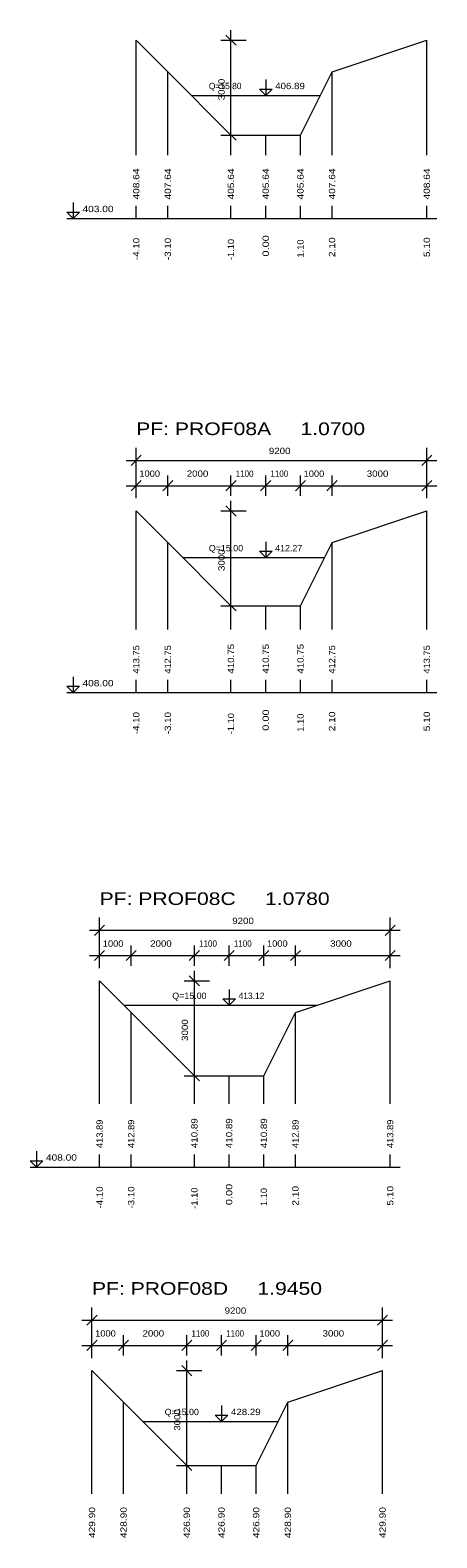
# Model space of a CAD drawing. Extents: x 7 to 442, y -393 to 441.
# Drawn here: x 175.74 to 188.62, y 95.9 to 143.59 of the extents above; entities that cross this region are included whole.
import ezdxf

# ---------------------------------------------------------------- set-up
doc = ezdxf.new("R2010")
doc.units = 0
doc.header["$LTSCALE"] = 0.08
doc.layers.add('7', color=7, linetype='Continuous', lineweight=13)

msp = doc.modelspace()

# ---------------------------------------------------------------- linework, layer by layer
at = {"layer": '7'}
for p, q in [((182.101, 140.111), (182.101, 143.591)), ((179.101, 139.634), (179.101, 143.271)), ((181.781, 143.271), (182.581, 143.271)), ((182.261, 143.111), (181.941, 143.431)), ((188.301, 139.634), (188.301, 143.271)), ((180.101, 139.634), (180.101, 142.271)), ((185.301, 139.634), (185.301, 142.271)), ((180.847, 141.525), (184.928, 141.525)), ((181.781, 140.271), (182.581, 140.271)), ((182.261, 140.111), (181.941, 140.431)), ((182.101, 139.634), (182.101, 140.271)), ((183.201, 139.634), (183.201, 140.271)), ((184.301, 139.634), (184.301, 140.271)), ((179.101, 137.634), (179.101, 138.034)), ((180.101, 137.634), (180.101, 138.034)), ((182.101, 137.634), (182.101, 138.034)), ((183.201, 137.634), (183.201, 138.034)), ((184.301, 137.634), (184.301, 138.034)), ((185.301, 137.634), (185.301, 138.034)), ((188.301, 137.634), (188.301, 138.034)), ((176.901, 137.634), (188.621, 137.634)), ((179.101, 128.781), (179.101, 130.381)), ((188.301, 128.781), (188.301, 130.381)), ((178.781, 129.981), (188.621, 129.981)), ((178.941, 129.821), (179.261, 130.141)), ((188.141, 129.821), (188.461, 130.141)), ((178.941, 129.021), (179.261, 129.341)), ((179.101, 128.861), (179.101, 129.501)), ((179.941, 129.021), (180.261, 129.341)), ((180.101, 128.861), (180.101, 129.501)), ((181.941, 129.021), (182.261, 129.341)), ((182.101, 128.861), (182.101, 129.501)), ((183.041, 129.021), (183.361, 129.341)), ((183.201, 128.861), (183.201, 129.501)), ((184.141, 129.021), (184.461, 129.341)), ((184.301, 128.861), (184.301, 129.501)), ((185.141, 129.021), (185.461, 129.341)), ((185.301, 128.861), (185.301, 129.501)), ((188.141, 129.021), (188.461, 129.341)), ((188.301, 128.861), (188.301, 129.501)), ((178.781, 129.181), (188.621, 129.181)), ((179.101, 124.634), (179.101, 128.381)), ((181.781, 128.381), (182.581, 128.381)), ((182.261, 128.221), (181.941, 128.541)), ((182.101, 125.221), (182.101, 128.701)), ((188.301, 124.634), (188.301, 128.381)), ((180.101, 124.634), (180.101, 127.381)), ((185.301, 124.634), (185.301, 127.381)), ((180.577, 126.904), (185.063, 126.904)), ((182.261, 125.221), (181.941, 125.541)), ((181.781, 125.381), (182.581, 125.381)), ((182.101, 124.634), (182.101, 125.381)), ((183.201, 124.634), (183.201, 125.381)), ((184.301, 124.634), (184.301, 125.381)), ((176.901, 122.634), (188.621, 122.634)), ((179.101, 122.634), (179.101, 123.034)), ((180.101, 122.634), (180.101, 123.034)), ((182.101, 122.634), (182.101, 123.034)), ((183.201, 122.634), (183.201, 123.034)), ((184.301, 122.634), (184.301, 123.034)), ((185.301, 122.634), (185.301, 123.034)), ((188.301, 122.634), (188.301, 123.034)), ((177.942, 113.916), (177.942, 115.516)), ((187.142, 113.916), (187.142, 115.516)), ((177.622, 115.116), (187.462, 115.116)), ((177.782, 114.956), (178.102, 115.276)), ((186.982, 114.956), (187.302, 115.276)), ((177.782, 114.156), (178.102, 114.476)), ((177.942, 113.996), (177.942, 114.636)), ((178.782, 114.156), (179.102, 114.476)), ((178.942, 113.996), (178.942, 114.636)), ((180.782, 114.156), (181.102, 114.476)), ((180.942, 113.996), (180.942, 114.636)), ((181.882, 114.156), (182.202, 114.476)), ((182.042, 113.996), (182.042, 114.636)), ((182.982, 114.156), (183.302, 114.476)), ((183.142, 113.996), (183.142, 114.636)), ((183.982, 114.156), (184.302, 114.476)), ((184.142, 113.996), (184.142, 114.636)), ((186.982, 114.156), (187.302, 114.476)), ((187.142, 113.996), (187.142, 114.636)), ((177.622, 114.316), (187.462, 114.316)), ((177.942, 109.627), (177.942, 113.516)), ((180.622, 113.516), (181.422, 113.516)), ((181.102, 113.356), (180.782, 113.676)), ((180.942, 110.356), (180.942, 113.836)), ((187.142, 109.627), (187.142, 113.516)), ((178.713, 112.745), (184.829, 112.745)), ((178.942, 109.627), (178.942, 112.516)), ((184.142, 109.627), (184.142, 112.516)), ((181.102, 110.356), (180.782, 110.676)), ((180.622, 110.516), (181.422, 110.516)), ((180.942, 109.627), (180.942, 110.516)), ((182.042, 109.627), (182.042, 110.516)), ((183.142, 109.627), (183.142, 110.516)), ((177.942, 107.627), (177.942, 108.027)), ((178.942, 107.627), (178.942, 108.027)), ((180.942, 107.627), (180.942, 108.027)), ((182.042, 107.627), (182.042, 108.027)), ((183.142, 107.627), (183.142, 108.027)), ((184.142, 107.627), (184.142, 108.027)), ((187.142, 107.627), (187.142, 108.027)), ((175.742, 107.627), (187.462, 107.627)), ((177.701, 101.585), (177.701, 103.185)), ((186.901, 101.585), (186.901, 103.185)), ((177.381, 102.785), (187.221, 102.785)), ((177.541, 102.625), (177.861, 102.945)), ((186.741, 102.625), (187.061, 102.945)), ((177.541, 101.825), (177.861, 102.145)), ((177.701, 101.665), (177.701, 102.305)), ((178.541, 101.825), (178.861, 102.145)), ((178.701, 101.665), (178.701, 102.305)), ((180.541, 101.825), (180.861, 102.145)), ((180.701, 101.665), (180.701, 102.305)), ((181.641, 101.825), (181.961, 102.145)), ((181.801, 101.665), (181.801, 102.305)), ((182.741, 101.825), (183.061, 102.145)), ((182.901, 101.665), (182.901, 102.305)), ((183.741, 101.825), (184.061, 102.145)), ((183.901, 101.665), (183.901, 102.305)), ((186.741, 101.825), (187.061, 102.145)), ((186.901, 101.665), (186.901, 102.305)), ((177.381, 101.985), (187.221, 101.985)), ((177.701, 97.289), (177.701, 101.185)), ((180.381, 101.185), (181.181, 101.185)), ((180.861, 101.025), (180.541, 101.345)), ((180.701, 98.025), (180.701, 101.505)), ((186.901, 97.289), (186.901, 101.185)), ((178.701, 97.289), (178.701, 100.185)), ((183.901, 97.289), (183.901, 100.185)), ((179.307, 99.579), (183.598, 99.579)), ((180.861, 98.025), (180.541, 98.345)), ((180.381, 98.185), (181.181, 98.185)), ((180.701, 97.289), (180.701, 98.185)), ((181.801, 97.289), (181.801, 98.185)), ((182.901, 97.289), (182.901, 98.185))]:
    msp.add_line(p, q, dxfattribs=at)
for points in [[(179.101, 143.271), (180.101, 142.271), (182.101, 140.271), (183.201, 140.271), (184.301, 140.271), (185.301, 142.271), (188.301, 143.271)], [(183.201, 142.025), (183.201, 141.525), (183.001, 141.725), (183.401, 141.725), (183.201, 141.525)], [(177.101, 138.134), (177.101, 137.634), (176.901, 137.834), (177.301, 137.834), (177.101, 137.634)], [(179.101, 128.381), (180.101, 127.381), (182.101, 125.381), (183.201, 125.381), (184.301, 125.381), (185.301, 127.381), (188.301, 128.381)], [(183.201, 127.404), (183.201, 126.904), (183.001, 127.104), (183.401, 127.104), (183.201, 126.904)], [(177.101, 123.134), (177.101, 122.634), (176.901, 122.834), (177.301, 122.834), (177.101, 122.634)], [(177.942, 113.516), (178.942, 112.516), (180.942, 110.516), (182.042, 110.516), (183.142, 110.516), (184.142, 112.516), (187.142, 113.516)], [(182.042, 113.245), (182.042, 112.745), (181.842, 112.945), (182.242, 112.945), (182.042, 112.745)], [(175.942, 108.127), (175.942, 107.627), (175.742, 107.827), (176.142, 107.827), (175.942, 107.627)], [(177.701, 101.185), (178.701, 100.185), (180.701, 98.185), (181.801, 98.185), (182.901, 98.185), (183.901, 100.185), (186.901, 101.185)], [(181.801, 100.079), (181.801, 99.579), (181.601, 99.779), (182.001, 99.779), (181.801, 99.579)]]:
    msp.add_lwpolyline(points, dxfattribs=at)

# ---------------------------------------------------------------- texts
for s, p in [('Q=15.80', (181.401, 141.725)), ('413.12', (182.342, 112.945))]:
    msp.add_text(s, height=0.2, dxfattribs=at).set_placement(p)
for s, width, p in [('3000', 1.15, (181.901, 141.371)), ('408.64 ', 1.2, (179.201, 138.234)), ('407.64 ', 1.2, (180.201, 138.234)), ('405.64 ', 1.2, (182.201, 138.234)), ('405.64 ', 1.2, (183.301, 138.234)), ('405.64 ', 1.2, (184.401, 138.234)), ('407.64 ', 1.2, (185.401, 138.234)), ('408.64 ', 1.2, (188.401, 138.234)), (' -4.10 ', 1.15, (179.201, 136.234)), (' -3.10 ', 1.15, (180.201, 136.234)), (' -1.10 ', 1.1, (182.201, 136.234)), ('  0.00 ', 1.3, (183.301, 136.234)), ('  1.10 ', 1.1, (184.401, 136.234)), ('  2.10 ', 1.2, (185.401, 136.234)), ('  5.10 ', 1.2, (188.401, 136.234)), ('3000', 1.15, (181.901, 126.481)), ('413.75 ', 1.1, (179.201, 123.234)), ('412.75 ', 1.1, (180.201, 123.234)), ('410.75 ', 1.15, (182.201, 123.234)), ('410.75 ', 1.15, (183.301, 123.234)), ('410.75 ', 1.15, (184.401, 123.234)), ('412.75 ', 1.1, (185.401, 123.234)), ('413.75 ', 1.1, (188.401, 123.234)), (' -4.10 ', 1.15, (179.201, 121.234)), (' -3.10 ', 1.15, (180.201, 121.234)), (' -1.10 ', 1.1, (182.201, 121.234)), ('  0.00 ', 1.3, (183.301, 121.234)), ('  1.10 ', 1.1, (184.401, 121.234)), ('  2.10 ', 1.2, (185.401, 121.234)), ('  5.10 ', 1.2, (188.401, 121.234)), ('3000', 1.15, (180.742, 111.616)), ('413.89 ', 1.1, (178.042, 108.227)), ('412.89 ', 1.1, (179.042, 108.227)), ('410.89 ', 1.15, (181.042, 108.227)), ('410.89 ', 1.15, (182.142, 108.227)), ('410.89 ', 1.15, (183.242, 108.227)), ('412.89 ', 1.1, (184.242, 108.227)), ('413.89 ', 1.1, (187.242, 108.227)), (' -4.10 ', 1.15, (178.042, 106.227)), (' -3.10 ', 1.15, (179.042, 106.227)), (' -1.10 ', 1.1, (181.042, 106.227)), ('  0.00 ', 1.3, (182.142, 106.227)), ('  1.10 ', 1.1, (183.242, 106.227)), ('  2.10 ', 1.2, (184.242, 106.227)), ('  5.10 ', 1.2, (187.242, 106.227)), ('3000', 1.15, (180.501, 99.285)), ('429.90 ', 1.2, (177.801, 95.889)), ('428.90 ', 1.2, (178.801, 95.889)), ('426.90 ', 1.2, (180.801, 95.889)), ('426.90 ', 1.2, (181.901, 95.889)), ('426.90 ', 1.2, (183.001, 95.889)), ('428.90 ', 1.2, (184.001, 95.889)), ('429.90 ', 1.2, (187.001, 95.889))]:
    msp.add_text(s, height=0.2, rotation=90, dxfattribs=dict(at, width=width)).set_placement(p)
for s, height, width, p in [('406.89', 0.2, 1.15, (183.501, 141.725)), ('403.00', 0.2, 1.2, (177.401, 137.834)), ('PF: PROF08A     1.0700', 0.4, 1.25, (179.101, 130.781)), ('9200', 0.2, 1.15, (183.301, 130.181)), ('1000', 0.2, 1.1, (179.201, 129.461)), ('2000', 0.2, 1.15, (180.701, 129.461)), ('1100', 0.2, 0.95, (182.251, 129.461)), ('1100', 0.2, 0.95, (183.351, 129.461)), ('1000', 0.2, 1.1, (184.401, 129.461)), ('3000', 0.2, 1.15, (186.401, 129.461)), ('Q=15.00', 0.2, 1.05, (181.401, 127.104)), ('412.27', 0.2, 1.05, (183.501, 127.104)), ('408.00', 0.2, 1.2, (177.401, 122.834)), ('PF: PROF08C     1.0780', 0.4, 1.25, (177.942, 115.916)), ('9200', 0.2, 1.15, (182.142, 115.316)), ('1000', 0.2, 1.1, (178.042, 114.596)), ('2000', 0.2, 1.15, (179.542, 114.596)), ('1100', 0.2, 0.95, (181.092, 114.596)), ('1100', 0.2, 0.95, (182.192, 114.596)), ('1000', 0.2, 1.1, (183.242, 114.596)), ('3000', 0.2, 1.15, (185.242, 114.596)), ('Q=15.00', 0.2, 1.05, (180.242, 112.945)), ('408.00', 0.2, 1.2, (176.242, 107.827)), ('PF: PROF08D     1.9450', 0.4, 1.25, (177.701, 103.585)), ('9200', 0.2, 1.15, (181.901, 102.985)), ('1000', 0.2, 1.1, (177.801, 102.265)), ('2000', 0.2, 1.15, (179.301, 102.265)), ('1100', 0.2, 0.95, (180.851, 102.265)), ('1100', 0.2, 0.95, (181.951, 102.265)), ('1000', 0.2, 1.1, (183.001, 102.265)), ('3000', 0.2, 1.15, (185.001, 102.265)), ('Q=15.00', 0.2, 1.05, (180.001, 99.779)), ('428.29', 0.2, 1.15, (182.101, 99.779))]:
    msp.add_text(s, height=height, dxfattribs=dict(at, width=width)).set_placement(p)

doc.saveas('drawing.dxf')
